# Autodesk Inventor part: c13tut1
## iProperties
Shininess: 64.0
Angle Display Precision: 2
Document Length Units: 11269
Document Angle Units: 11279
Document Time Units: 11290
Document Mass Units: 11283
Document Length Units Precision: 3
Document Angle Units Precision: 2
Compacted: True
Created: 2002-04
Part Number: c13tut1
Document SubType Name: Modeling
Density: 1 g/cm^3
Density: 0.0
Volumn: 0.0
Area: 0.0
PropertySet Name: Model Information
Control State: 0
Master: False
Checked Out: False
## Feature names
1. Extrusion1
